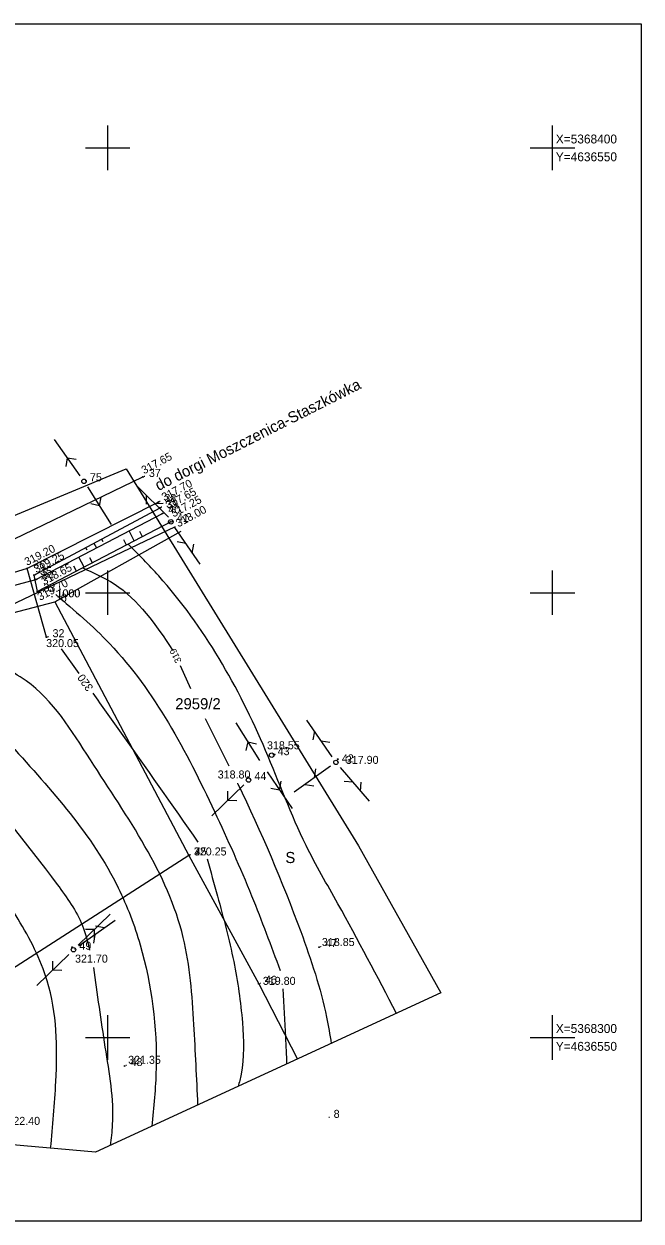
# Model space of a CAD drawing. Extents: x 4632591 to 4651936, y 5351032 to 5369988.
# Drawn here: x 4636490.6 to 4636560, y 5368279.4 to 5368413.9 of the extents above; entities that cross this region are included whole.
import ezdxf

# ---------------------------------------------------------------- set-up
doc = ezdxf.new("R2010")
doc.units = 0
for name, color, linetype in [('EBUPP_312', 7, 'Continuous'), ('EDZPD_211', 7, 'Continuous'), ('EDZPD_219', 7, 'Continuous'), ('EKLPK_209', 7, 'Continuous'), ('EUZPU_424', 7, 'Continuous'), ('SDRPK_420', 7, 'Continuous'), ('SDRPK_432', 7, 'Continuous'), ('SDRPT_414', 7, 'Continuous'), ('UEEPA_510', 7, 'Continuous'), ('UEETA_516', 7, 'Continuous'), ('UTTPA_510', 7, 'Continuous'), ('UTTTA_521', 7, 'Continuous'), ('UWWPO_581', 7, 'Continuous'), ('Warstwa 25', 7, 'Continuous'), ('Warstwa 40', 7, 'Continuous'), ('Warstwa 60', 7, 'Continuous'), ('Warstwa 62', 7, 'Continuous'), ('WUKPS_820', 7, 'Continuous'), ('WUKPS_823', 7, 'Continuous'), ('WUKPS_824', 7, 'Continuous'), ('WWRPH_811', 7, 'Continuous'), ('WWRPH_812', 7, 'Continuous'), ('WWRPH_814', 7, 'Continuous'), ('WWRPP_801', 7, 'Continuous')]:
    doc.layers.add(name, color=color, linetype=linetype)

msp = doc.modelspace()

# ---------------------------------------------------------------- linework, layer by layer
at = {"layer": 'EBUPP_312'}
msp.add_lwpolyline([(4636370.172181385, 5368413.935757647), (4636559.955478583, 5368413.935757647), (4636559.955478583, 5368279.356721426), (4636370.172181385, 5368279.356721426)], close=True, dxfattribs=at)
at = {"layer": 'EDZPD_219'}
for p, q in [((4636494.0600000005, 5368348.98), (4636508.250440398, 5368356.906119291)), ((4636458.19, 5368339.600000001), (4636494.0600000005, 5368348.98)), ((4636494.0600000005, 5368348.98), (4636509.11, 5368320.47)), ((4636509.11, 5368320.47), (4636486.62, 5368306.01)), ((4636509.11, 5368320.47), (4636517, 5368306.03)), ((4636517, 5368306.03), (4636521.339417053, 5368297.570101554))]:
    msp.add_line(p, q, dxfattribs=at)
at = {"layer": 'EUZPU_424'}
msp.add_line((4636493.13, 5368344.99), (4636490.96, 5368352.73), dxfattribs=at)
at = {"layer": 'SDRPK_420'}
for points in [[(4636414.24, 5368319.9), (4636428.86, 5368331.73), (4636444.96, 5368341.16), (4636463.62, 5368348.49), (4636484.97, 5368353.88), (4636503.96, 5368363.01)], [(4636505.7, 5368360.19), (4636490.96, 5368352.73), (4636485.69, 5368351.12), (4636464.29, 5368345.92), (4636446.0600000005, 5368338.7), (4636430.26, 5368328.78), (4636426.21, 5368325.83), (4636416.13, 5368317.850000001)]]:
    msp.add_lwpolyline(points, dxfattribs=at)
at = {"layer": 'SDRPT_414'}
msp.add_line((4636485.98, 5368349.87), (4636491.93, 5368351.48), dxfattribs=at)
at = {"layer": 'UEEPA_510'}
for centre in [(4636497.33, 5368362.5200000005), (4636518.43, 5368331.73), (4636525.65, 5368330.92), (4636515.83, 5368328.93), (4636496.15, 5368309.86)]:
    msp.add_circle(centre, 0.25, dxfattribs=at)
at = {"layer": 'UEETA_516'}
for p, q in [((4636496.896753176, 5368363.132206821), (4636494.008441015, 5368367.213585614)), ((4636495.452597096, 5368365.172896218), (4636495.2838974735, 5368364.187381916)), ((4636495.452597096, 5368365.172896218), (4636496.4381113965, 5368365.004196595)), ((4636497.72860654, 5368361.884694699), (4636500.385983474, 5368357.649326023)), ((4636499.057295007, 5368359.767010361), (4636499.28042304, 5368360.74164459)), ((4636499.057295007, 5368359.767010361), (4636498.082660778, 5368359.990138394)), ((4636517.08516865, 5368331.12074702), (4636514.422524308, 5368335.352806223)), ((4636515.75384648, 5368333.236776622), (4636515.531931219, 5368332.2618655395)), ((4636515.75384648, 5368333.236776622), (4636516.728757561, 5368333.014861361)), ((4636517.910201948, 5368329.868416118), (4636520.747779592, 5368325.7516026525)), ((4636515.291388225, 5368328.408083), (4636511.700643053, 5368324.928636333)), ((4636519.3289907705, 5368327.810009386), (4636519.5098747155, 5368328.793360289)), ((4636513.496015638, 5368326.668359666), (4636513.511753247, 5368327.668084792)), ((4636519.3289907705, 5368327.810009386), (4636518.345639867, 5368327.990893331)), ((4636513.496015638, 5368326.668359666), (4636514.495740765, 5368326.652622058)), ((4636496.688611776, 5368310.381917), (4636500.279356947, 5368313.861363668)), ((4636498.483984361, 5368312.121640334), (4636497.484259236, 5368312.137377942)), ((4636498.483984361, 5368312.121640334), (4636498.468246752, 5368311.121915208)), ((4636495.61493464, 5368309.334447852), (4636492.047832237, 5368305.830766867)), ((4636493.831383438, 5368307.58260736), (4636493.840351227, 5368308.582416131)), ((4636493.831383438, 5368307.58260736), (4636494.831192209, 5368307.573639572))]:
    msp.add_line(p, q, dxfattribs=at)
at = {"layer": 'UTTPA_510'}
msp.add_circle((4636507.100000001, 5368357.96), 0.25, dxfattribs=at)
at = {"layer": 'UTTTA_521'}
for p, q in [((4636506.816909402, 5368358.487555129), (4636503.262972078, 5368362.00458932)), ((4636504.329153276, 5368360.949479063), (4636504.334371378, 5368359.949643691)), ((4636505.248201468, 5368360.039974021), (4636506.24803684, 5368360.045192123)), ((4636507.524275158, 5368357.341541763), (4636510.3527762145, 5368353.218486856)), ((4636508.772775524, 5368355.521625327), (4636507.789825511, 5368355.704675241)), ((4636509.504225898, 5368354.455403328), (4636509.687275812, 5368355.438353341)), ((4636525.225724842, 5368331.5384582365), (4636522.3972237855, 5368335.661513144)), ((4636523.245774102, 5368334.424596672), (4636523.062724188, 5368333.441646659)), ((4636523.977224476, 5368333.358374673), (4636524.960174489, 5368333.1753247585)), ((4636525.039588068, 5368330.484227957), (4636520.970175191, 5368327.579081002)), ((4636523.243349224, 5368329.201896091), (4636523.407976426, 5368330.188098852)), ((4636526.138987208, 5368330.351324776), (4636529.398901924, 5368326.560156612)), ((4636522.190999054, 5368328.450625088), (4636523.177201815, 5368328.285997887)), ((4636527.577913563, 5368328.677903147), (4636526.580890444, 5368328.753022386)), ((4636528.420927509, 5368327.697507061), (4636528.496046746, 5368328.69453018)), ((4636496.760411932, 5368310.295772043), (4636500.829824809, 5368313.200918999)), ((4636499.609000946, 5368312.329374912), (4636498.622798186, 5368312.494002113)), ((4636498.556650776, 5368311.578103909), (4636498.392023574, 5368310.591901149))]:
    msp.add_line(p, q, dxfattribs=at)
at = {"layer": 'UWWPO_581'}
msp.add_lwpolyline([(4636422.455049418, 5368310.7801110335), (4636459.845473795, 5368334.612790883), (4636507.616337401, 5368357.428321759)], dxfattribs=at)
at = {"layer": 'Warstwa 40'}
for p, q in [((4636483.866787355, 5368356.32149351), (4636502.069273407, 5368363.930729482)), ((4636502.069273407, 5368363.930729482), (4636528.179396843, 5368321.557729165)), ((4636528.179396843, 5368321.557729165), (4636537.429840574, 5368304.996450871)), ((4636537.429840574, 5368304.996450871), (4636498.637657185, 5368287.09236623)), ((4636498.637657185, 5368287.09236623), (4636483.568385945, 5368288.435172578))]:
    msp.add_line(p, q, dxfattribs=at)
at = {"layer": 'Warstwa 60'}
for p, q in [((4636500, 5368397.5), (4636500, 5368402.5)), ((4636550, 5368397.5), (4636550, 5368402.5)), ((4636497.5, 5368400), (4636502.5, 5368400)), ((4636547.5, 5368400), (4636552.5, 5368400)), ((4636500, 5368347.5), (4636500, 5368352.5)), ((4636550, 5368347.5), (4636550, 5368352.5)), ((4636497.5, 5368350), (4636502.5, 5368350)), ((4636547.5, 5368350), (4636552.5, 5368350)), ((4636500, 5368297.5), (4636500, 5368302.5)), ((4636550, 5368297.5), (4636550, 5368302.5)), ((4636497.5, 5368300), (4636502.5, 5368300)), ((4636547.5, 5368300), (4636552.5, 5368300))]:
    msp.add_line(p, q, dxfattribs=at)
at = {"layer": 'WUKPS_820'}
for p, q in [((4636502.98498577, 5368355.80923354), (4636502.39397294, 5368356.93982345)), ((4636503.9141893, 5368356.29489725), (4636503.618846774, 5368356.85987865)), ((4636497.51984392, 5368355.07844856), (4636497.66209263, 5368354.812092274)), ((4636498.44254159, 5368355.57137879), (4636498.73198913, 5368355.02940026)), ((4636499.299332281, 5368356.02909971), (4636499.446360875, 5368355.75379614)), ((4636502.12215391, 5368355.35826008), (4636501.82648888, 5368355.923858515)), ((4636497.34339287, 5368352.86056096), (4636496.75008122, 5368353.99554913)), ((4636498.2725964, 5368353.34622468), (4636497.976148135, 5368353.91332165)), ((4636496.48056101, 5368352.40958751), (4636496.183706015, 5368352.97746267))]:
    msp.add_line(p, q, dxfattribs=at)
at = {"layer": 'WUKPS_823'}
msp.add_lwpolyline([(4636507.100000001, 5368357.96), (4636492.100000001, 5368350.12), (4636491.72, 5368351.98), (4636505.89, 5368359.55)], dxfattribs=at)
at = {"layer": 'WUKPS_824'}
msp.add_line((4636491.93, 5368351.48), (4636506.15, 5368358.9), dxfattribs=at)
at = {"layer": 'WWRPH_811'}
for p, q in [((4636508.155926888, 5368341.801422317), (4636509.317737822, 5368339.208592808)), ((4636510.951171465, 5368335.867811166), (4636513.632897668, 5368330.530566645))]:
    msp.add_line(p, q, dxfattribs=at)
for points in [[(4636497.195297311, 5368352.783142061), (4636500.736786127, 5368350.982385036), (4636507.298240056, 5368343.546828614)], [(4636489.130373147, 5368332.827607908), (4636501.184388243, 5368316.815423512), (4636503.646199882, 5368310.399793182), (4636505.436608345, 5368296.449527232), (4636504.969202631, 5368290.014617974)], [(4636514.578758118, 5368328.596759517), (4636514.612451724, 5368328.527678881), (4636521.699485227, 5368311.891800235), (4636524.608898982, 5368302.26835474), (4636525.1293224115, 5368299.319288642)], [(4636493.580707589, 5368287.542985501), (4636494.171955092, 5368295.032120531), (4636493.202150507, 5368306.371374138), (4636489.919734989, 5368313.309206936), (4636480.4977891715, 5368326.439070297)]]:
    msp.add_spline(points, degree=3, dxfattribs=at)
at = {"layer": 'WWRPH_812'}
for points in [[(4636532.46165037, 5368302.703440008), (4636525.877104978, 5368315.025015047), (4636522.29628805, 5368321.589846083), (4636517.7456665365, 5368332.257696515), (4636505.735009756, 5368351.877589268), (4636502.307661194, 5368355.45520425)], [(4636494.160169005, 5368349.796297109), (4636500.214583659, 5368344.2683532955), (4636512.00143938, 5368325.394464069), (4636516.17905913, 5368315.92021928), (4636519.3898929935, 5368307.506782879)], [(4636466.379731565, 5368342.356296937), (4636471.344247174, 5368339.643131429), (4636476.790072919, 5368336.360715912), (4636483.205703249, 5368330.616488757), (4636494.321155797, 5368317.188425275), (4636497.155969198, 5368312.563203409), (4636497.963317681, 5368309.823982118)], [(4636510.147538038, 5368292.404618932), (4636509.688828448, 5368301.447750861), (4636508.495222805, 5368311.220397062), (4636498.051173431, 5368331.213291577), (4636490.814939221, 5368340.090733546), (4636488.1301364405, 5368341.737711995)], [(4636498.404184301, 5368307.867663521), (4636499.692381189, 5368298.91133887), (4636500.512985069, 5368290.183097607), (4636500.279698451, 5368287.8502314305)], [(4636519.684851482, 5368305.447885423), (4636519.983677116, 5368300.03034416), (4636520.11521021, 5368297.0050830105)]]:
    msp.add_spline(points, degree=3, dxfattribs=at)
at = {"layer": 'WWRPH_814'}
msp.add_line((4636494.768757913, 5368343.671550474), (4636496.742730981, 5368340.901258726), dxfattribs=at)
for points in [[(4636498.317707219, 5368338.690922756), (4636501.3335889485, 5368334.458406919), (4636510.143672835, 5368321.96491987)], [(4636511.175924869, 5368320.085641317), (4636512.337140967, 5368315.882919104), (4636514.164849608, 5368308.5347843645), (4636515.134654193, 5368301.67155192), (4636514.985453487, 5368295.8527244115), (4636514.66989037, 5368294.49185847)]]:
    msp.add_spline(points, degree=3, dxfattribs=at)
at = {"layer": 'WWRPP_801'}
for centre in [(4636503.96, 5368363.01), (4636505.7, 5368360.19), (4636505.89, 5368359.55), (4636506.15, 5368358.9), (4636507.100000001, 5368357.96), (4636490.96, 5368352.73), (4636491.72, 5368351.98), (4636491.93, 5368351.48), (4636492.100000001, 5368350.12), (4636493.13, 5368344.99), (4636518.765701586, 5368331.804600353), (4636525.85515097, 5368331.274351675), (4636515.774049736, 5368329.265701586), (4636509.11, 5368320.47), (4636496.010124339, 5368310.158401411), (4636523.78, 5368310.15), (4636517, 5368306.03), (4636501.9, 5368296.79)]:
    msp.add_circle(centre, 0.045, dxfattribs=at)

# ---------------------------------------------------------------- texts
at = {"layer": 'EDZPD_211'}
msp.add_text('2959/2', height=1.25, dxfattribs=at).set_placement((4636507.589699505, 5368336.888101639))
at = {"layer": 'EKLPK_209'}
msp.add_text('S', height=1.25, dxfattribs=at).set_placement((4636519.969689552, 5368319.603611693))
at = {"layer": 'SDRPK_432'}
msp.add_text('do dorgi Moszczenica-Staszkówka', height=1.25, rotation=26.844237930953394, dxfattribs=at).set_placement((4636505.714028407, 5368361.419440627))
at = {"layer": 'Warstwa 25'}
for s, p in [(' X=5368400 ', (4636550, 5368400.5)), (' Y=4636550 ', (4636550, 5368398.5)), (' X=5368300 ', (4636550, 5368300.5)), (' Y=4636550 ', (4636550, 5368298.5))]:
    msp.add_text(s, height=1, dxfattribs=at).set_placement(p)
at = {"layer": 'Warstwa 62'}
for s, p in [('. 75', (4636497.33, 5368362.5200000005)), ('. 37', (4636503.96, 5368363.01)), ('. 38', (4636505.7, 5368360.19)), ('. 39', (4636505.89, 5368359.55)), ('. 40', (4636506.15, 5368358.9)), ('. 41', (4636507.100000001, 5368357.96)), ('. 36', (4636490.96, 5368352.73)), ('. 35', (4636491.72, 5368351.98)), ('. 34', (4636491.93, 5368351.48)), ('. 33', (4636492.100000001, 5368350.12)), ('. 1000', (4636493.5600000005, 5368349.47)), ('. 1000', (4636493.5600000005, 5368349.47)), ('. 1000', (4636493.58, 5368349.48)), ('. 1000', (4636493.58, 5368349.48)), ('. 6', (4636494.0600000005, 5368348.98)), ('. 32', (4636493.13, 5368344.99)), ('. 43', (4636518.43, 5368331.73)), ('. 42', (4636525.65, 5368330.92)), ('. 44', (4636515.83, 5368328.93)), ('. 7', (4636509.0600000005, 5368320.44)), ('. 45', (4636509.11, 5368320.47)), ('. 49', (4636496.15, 5368309.86)), ('. 47', (4636523.78, 5368310.15)), ('. 46', (4636517, 5368306.03)), ('. 48', (4636501.9, 5368296.79)), ('. 8', (4636524.73, 5368290.96))]:
    msp.add_text(s, height=0.9, dxfattribs=at).set_placement(p)
at = {"layer": 'WWRPH_811'}
msp.add_text('319', height=0.75, rotation=116.12423709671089, dxfattribs=at).set_placement((4636508.335827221, 5368342.307131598))
at = {"layer": 'WWRPH_814'}
msp.add_text('320', height=0.9, rotation=125.47179536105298, dxfattribs=at).set_placement((4636498.423051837, 5368339.318539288))
at = {"layer": 'WWRPP_801'}
for s, rotation, p in [('317.65', 28.112347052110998, (4636504.08348293, 5368363.296626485)), ('317.70', 28.112347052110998, (4636506.358793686, 5368360.275312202)), ('317.65', 28.112347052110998, (4636506.806395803, 5368359.342807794)), ('317.25', 28.112347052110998, (4636507.403198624, 5368358.447603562)), ('318.00', 28.112347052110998, (4636507.944051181, 5368357.328598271)), ('319.20', 26.844237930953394, (4636490.916520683, 5368353.001777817)), ('319.25', 28.112347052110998, (4636491.9795757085, 5368352.162523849)), ('318.65', 28.112347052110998, (4636492.837479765, 5368350.8197175)), ('319.70', 28.112347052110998, (4636492.389877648, 5368349.066609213))]:
    msp.add_text(s, height=0.9, rotation=rotation, dxfattribs=at).set_placement(p)
for s, p in [('320.05', (4636493.079930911, 5368343.881884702)), ('318.55', (4636517.903198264, 5368332.39343039)), ('317.90', (4636526.761990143, 5368330.752222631)), ('318.80', (4636512.364122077, 5368329.111014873)), ('320.25', (4636509.678509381, 5368320.457373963)), ('318.85', (4636524.076377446, 5368310.274425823)), ('321.70', (4636496.325046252, 5368308.409417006)), ('319.80', (4636517.436946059, 5368305.910305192)), ('321.35', (4636502.293074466, 5368297.032863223)), ('322.40', (4636488.71581028, 5368290.169630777))]:
    msp.add_text(s, height=0.9, dxfattribs=at).set_placement(p)

doc.saveas('drawing.dxf')
